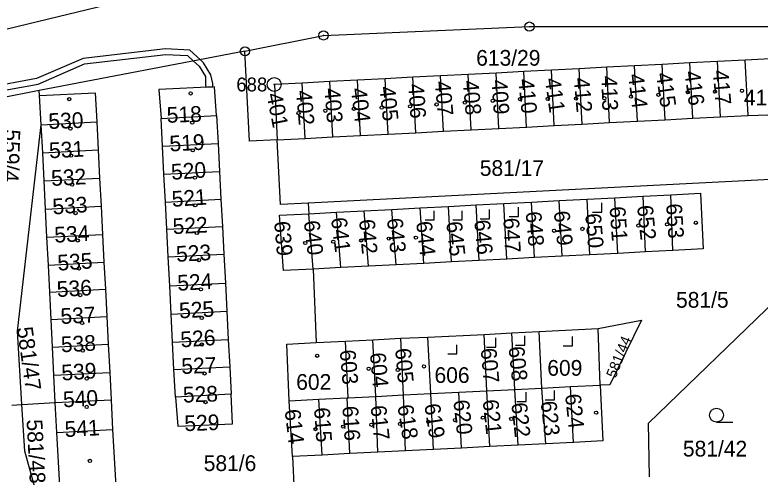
# Model space of a CAD drawing. Extents: x -758582 to -751794, y -998770 to -994350.
# Drawn here: x -756110.2 to -756029.6, y -995556.9 to -995507.3 of the extents above; entities that cross this region are included whole.
import ezdxf

# ---------------------------------------------------------------- set-up
doc = ezdxf.new("R2010")
doc.units = 0
for name, color, linetype in [('Hranice parcel', 7, 'Continuous'), ('Parcelní čísla', 7, 'Continuous'), ('Věcná břemena k části', 7, 'Continuous'), ('Značky bodu BP', 7, 'Continuous'), ('Značky budov', 7, 'Continuous'), ('Značky kultur', 7, 'Continuous')]:
    doc.layers.add(name, color=color, linetype=linetype)

msp = doc.modelspace()

# ---------------------------------------------------------------- linework, layer by layer
at = {"layer": 'Hranice parcel'}
for p, q in [((-756077.08, -995500.54), (-756125.07, -995512.2)), ((-756085.32, -995511.19), (-756107.59, -995515.44)), ((-756043.18, -995512.76), (-756046.18, -995512.92)), ((-756040.19, -995512.61), (-756043.18, -995512.76)), ((-756042.87, -995518.76), (-756043.18, -995512.76)), ((-756037.19, -995512.45), (-756040.19, -995512.61)), ((-756039.88, -995518.6), (-756040.19, -995512.61)), ((-756034.19, -995512.3), (-756037.19, -995512.45)), ((-756036.88, -995518.44), (-756037.19, -995512.45)), ((-756031.2, -995512.14), (-756034.19, -995512.3)), ((-756033.88, -995518.29), (-756034.19, -995512.3)), ((-756030.89, -995518.13), (-756031.2, -995512.14)), ((-756061.16, -995513.69), (-756064.15, -995513.85)), ((-756058.16, -995513.54), (-756061.16, -995513.69)), ((-756060.85, -995519.69), (-756061.16, -995513.69)), ((-756055.17, -995513.38), (-756058.16, -995513.54)), ((-756057.85, -995519.53), (-756058.16, -995513.54)), ((-756052.17, -995513.23), (-756055.17, -995513.38)), ((-756054.86, -995519.38), (-756055.17, -995513.38)), ((-756049.17, -995513.07), (-756052.17, -995513.23)), ((-756051.86, -995519.22), (-756052.17, -995513.23)), ((-756046.18, -995512.92), (-756049.17, -995513.07)), ((-756048.86, -995519.07), (-756049.17, -995513.07)), ((-756045.87, -995518.91), (-756046.18, -995512.92)), ((-756076.14, -995514.47), (-756079.13, -995514.62)), ((-756073.14, -995514.31), (-756076.14, -995514.47)), ((-756075.83, -995520.46), (-756076.14, -995514.47)), ((-756070.15, -995514.16), (-756073.14, -995514.31)), ((-756072.83, -995520.31), (-756073.14, -995514.31)), ((-756067.15, -995514), (-756070.15, -995514.16)), ((-756069.84, -995520.15), (-756070.15, -995514.16)), ((-756064.15, -995513.85), (-756067.15, -995514)), ((-756066.84, -995520), (-756067.15, -995514)), ((-756063.84, -995519.84), (-756064.15, -995513.85)), ((-756078.82, -995520.62), (-756079.13, -995514.62)), ((-756107.59, -995515.44), (-756111.98, -995516.28)), ((-756107.56, -995515.97), (-756107.59, -995515.44)), ((-756107.35, -995519.13), (-756107.56, -995515.97)), ((-756094.4, -995518.46), (-756088.39, -995518.15)), ((-756094.24, -995521.47), (-756094.4, -995518.46)), ((-756088.39, -995518.15), (-756088.23, -995521.16)), ((-756039.88, -995518.6), (-756036.88, -995518.44)), ((-756036.88, -995518.44), (-756033.88, -995518.29)), ((-756033.88, -995518.29), (-756030.89, -995518.13)), ((-756030.89, -995518.13), (-756026.86, -995517.98)), ((-756107.35, -995519.13), (-756101.36, -995518.82)), ((-756107.19, -995522.17), (-756107.35, -995519.13)), ((-756101.36, -995518.82), (-756101.2, -995521.86)), ((-756054.86, -995519.38), (-756051.86, -995519.22)), ((-756051.86, -995519.22), (-756048.86, -995519.07)), ((-756048.86, -995519.07), (-756045.87, -995518.91)), ((-756045.87, -995518.91), (-756042.87, -995518.76)), ((-756042.87, -995518.76), (-756039.88, -995518.6)), ((-756069.84, -995520.15), (-756066.84, -995520)), ((-756066.84, -995520), (-756063.84, -995519.84)), ((-756063.84, -995519.84), (-756060.85, -995519.69)), ((-756060.85, -995519.69), (-756057.85, -995519.53)), ((-756057.85, -995519.53), (-756054.86, -995519.38)), ((-756081.82, -995520.77), (-756078.82, -995520.62)), ((-756078.82, -995520.62), (-756075.83, -995520.46)), ((-756075.83, -995520.46), (-756072.83, -995520.31)), ((-756072.83, -995520.31), (-756069.84, -995520.15)), ((-756094.24, -995521.47), (-756088.23, -995521.16)), ((-756094.08, -995524.5), (-756094.24, -995521.47)), ((-756088.23, -995521.16), (-756088.07, -995524.19)), ((-756107.19, -995522.17), (-756101.2, -995521.86)), ((-756107.04, -995525.22), (-756107.19, -995522.17)), ((-756101.2, -995521.86), (-756101.04, -995524.91)), ((-756107.04, -995525.22), (-756101.04, -995524.91)), ((-756101.04, -995524.91), (-756100.88, -995527.95)), ((-756094.08, -995524.5), (-756088.07, -995524.19)), ((-756093.93, -995527.5), (-756094.08, -995524.5)), ((-756088.07, -995524.19), (-756087.92, -995527.18)), ((-756106.89, -995528.26), (-756107.04, -995525.22)), ((-756028.42, -995525.06), (-756078.5, -995527.61)), ((-756093.93, -995527.5), (-756087.92, -995527.18)), ((-756087.92, -995527.18), (-756087.76, -995530.13)), ((-756054.32, -995527.5), (-756051.32, -995527.34)), ((-756051.32, -995527.34), (-756048.32, -995527.18)), ((-756050.99, -995533.36), (-756051.32, -995527.34)), ((-756048.32, -995527.18), (-756045.32, -995527.03)), ((-756048, -995533.2), (-756048.32, -995527.18)), ((-756045.32, -995527.03), (-756042.26, -995526.87)), ((-756045, -995533.05), (-756045.32, -995527.03)), ((-756042.26, -995526.87), (-756039.26, -995526.71)), ((-756042.01, -995532.89), (-756042.26, -995526.87)), ((-756039.02, -995532.74), (-756039.26, -995526.71)), ((-756106.89, -995528.26), (-756100.88, -995527.95)), ((-756100.88, -995527.95), (-756100.73, -995531)), ((-756093.78, -995530.44), (-756093.93, -995527.5)), ((-756078.5, -995527.61), (-756078.42, -995528.77)), ((-756069.42, -995528.29), (-756066.37, -995528.13)), ((-756066.37, -995528.13), (-756063.32, -995527.97)), ((-756065.97, -995534.13), (-756066.37, -995528.13)), ((-756063.32, -995527.97), (-756060.32, -995527.81)), ((-756062.97, -995533.98), (-756063.32, -995527.97)), ((-756060.32, -995527.81), (-756057.32, -995527.66)), ((-756059.98, -995533.82), (-756060.32, -995527.81)), ((-756057.32, -995527.66), (-756054.32, -995527.5)), ((-756056.98, -995533.67), (-756057.32, -995527.66)), ((-756053.99, -995533.51), (-756054.32, -995527.5)), ((-756106.74, -995531.31), (-756106.89, -995528.26)), ((-756081.57, -995528.93), (-756078.42, -995528.77)), ((-756081.14, -995534.91), (-756081.57, -995528.93)), ((-756078.42, -995528.77), (-756075.42, -995528.61)), ((-756077.94, -995534.75), (-756078.42, -995528.77)), ((-756075.42, -995528.61), (-756072.42, -995528.45)), ((-756074.95, -995534.59), (-756075.42, -995528.61)), ((-756072.42, -995528.45), (-756069.42, -995528.29)), ((-756071.95, -995534.44), (-756072.42, -995528.45)), ((-756068.96, -995534.28), (-756069.42, -995528.29)), ((-756093.78, -995530.44), (-756087.76, -995530.13)), ((-756093.63, -995533.44), (-756093.78, -995530.44)), ((-756087.76, -995530.13), (-756087.61, -995533.12)), ((-756106.74, -995531.31), (-756100.73, -995531)), ((-756106.58, -995534.31), (-756106.74, -995531.31)), ((-756100.73, -995531), (-756100.57, -995534)), ((-756042.01, -995532.89), (-756045, -995533.05)), ((-756039.02, -995532.74), (-756042.01, -995532.89)), ((-756093.63, -995533.44), (-756087.61, -995533.12)), ((-756093.46, -995536.58), (-756093.63, -995533.44)), ((-756087.61, -995533.12), (-756087.44, -995536.27)), ((-756059.98, -995533.82), (-756062.97, -995533.98)), ((-756056.98, -995533.67), (-756059.98, -995533.82)), ((-756053.99, -995533.51), (-756056.98, -995533.67)), ((-756050.99, -995533.36), (-756053.99, -995533.51)), ((-756048, -995533.2), (-756050.99, -995533.36)), ((-756045, -995533.05), (-756048, -995533.2)), ((-756106.58, -995534.31), (-756100.57, -995534)), ((-756106.44, -995537.25), (-756106.58, -995534.31)), ((-756100.57, -995534), (-756100.42, -995536.94)), ((-756074.95, -995534.59), (-756077.94, -995534.75)), ((-756071.95, -995534.44), (-756074.95, -995534.59)), ((-756068.96, -995534.28), (-756071.95, -995534.44)), ((-756065.97, -995534.13), (-756068.96, -995534.28)), ((-756062.97, -995533.98), (-756065.97, -995534.13)), ((-756077.94, -995534.75), (-756081.14, -995534.91)), ((-756077.94, -995534.75), (-756077.6, -995542.71)), ((-756106.44, -995537.25), (-756100.42, -995536.94)), ((-756100.42, -995536.94), (-756100.27, -995539.89)), ((-756093.46, -995536.58), (-756087.44, -995536.27)), ((-756093.31, -995539.63), (-756093.46, -995536.58)), ((-756087.44, -995536.27), (-756087.28, -995539.31)), ((-756106.29, -995540.2), (-756106.44, -995537.25)), ((-756093.31, -995539.63), (-756087.28, -995539.31)), ((-756087.28, -995539.31), (-756087.13, -995542.36)), ((-756106.29, -995540.2), (-756100.27, -995539.89)), ((-756106.14, -995543.2), (-756106.29, -995540.2)), ((-756100.27, -995539.89), (-756100.11, -995542.88)), ((-756093.16, -995542.67), (-756093.31, -995539.63)), ((-756065.54, -995542.12), (-756059.45, -995541.82)), ((-756059.45, -995541.82), (-756056.45, -995541.66)), ((-756059.17, -995547.92), (-756059.45, -995541.82)), ((-756056.45, -995541.66), (-756053.51, -995541.5)), ((-756056.14, -995547.77), (-756056.45, -995541.66)), ((-756053.51, -995541.5), (-756047.11, -995541.17)), ((-756053.2, -995547.62), (-756053.51, -995541.5)), ((-756046.89, -995547.3), (-756047.11, -995541.17)), ((-756093.16, -995542.67), (-756087.13, -995542.36)), ((-756093, -995545.62), (-756093.16, -995542.67)), ((-756087.13, -995542.36), (-756086.97, -995545.31)), ((-756080.8, -995542.87), (-756077.6, -995542.71)), ((-756077.6, -995542.71), (-756074.45, -995542.55)), ((-756074.45, -995542.55), (-756071.48, -995542.39)), ((-756074.14, -995548.67), (-756074.45, -995542.55)), ((-756071.48, -995542.39), (-756068.47, -995542.24)), ((-756071.17, -995548.52), (-756071.48, -995542.39)), ((-756068.47, -995542.24), (-756065.54, -995542.12)), ((-756068.16, -995548.37), (-756068.47, -995542.24)), ((-756065.23, -995548.22), (-756065.54, -995542.12)), ((-756106.14, -995543.2), (-756100.11, -995542.88)), ((-756105.99, -995546.24), (-756106.14, -995543.2)), ((-756100.11, -995542.88), (-756099.95, -995545.93)), ((-756080.54, -995548.99), (-756080.8, -995542.87)), ((-756105.99, -995546.24), (-756099.95, -995545.93)), ((-756099.95, -995545.93), (-756099.8, -995548.88)), ((-756093, -995545.62), (-756086.97, -995545.31)), ((-756092.85, -995548.62), (-756093, -995545.62)), ((-756086.97, -995545.31), (-756086.82, -995548.3)), ((-756105.84, -995549.19), (-756105.99, -995546.24)), ((-756053.2, -995547.62), (-756050.12, -995547.46)), ((-756050.12, -995547.46), (-756046.89, -995547.3)), ((-756049.78, -995553.5), (-756050.12, -995547.46)), ((-756086.82, -995548.3), (-756092.85, -995548.62)), ((-756068.16, -995548.37), (-756065.23, -995548.22)), ((-756065.23, -995548.22), (-756062.18, -995548.07)), ((-756064.92, -995554.26), (-756065.23, -995548.22)), ((-756062.18, -995548.07), (-756059.17, -995547.92)), ((-756061.88, -995554.11), (-756062.18, -995548.07)), ((-756059.17, -995547.92), (-756056.14, -995547.77)), ((-756058.83, -995553.96), (-756059.17, -995547.92)), ((-756056.14, -995547.77), (-756053.2, -995547.62)), ((-756055.78, -995553.8), (-756056.14, -995547.77)), ((-756052.79, -995553.65), (-756053.2, -995547.62)), ((-756105.84, -995549.19), (-756099.8, -995548.88)), ((-756099.8, -995548.88), (-756099.63, -995552.12)), ((-756080.54, -995548.99), (-756077.33, -995548.83)), ((-756080.18, -995555.03), (-756080.54, -995548.99)), ((-756077.33, -995548.83), (-756074.26, -995548.68)), ((-756076.98, -995554.87), (-756077.33, -995548.83)), ((-756074.26, -995548.68), (-756074.14, -995548.67)), ((-756073.97, -995554.72), (-756074.26, -995548.68)), ((-756074.14, -995548.67), (-756071.17, -995548.52)), ((-756071.17, -995548.52), (-756068.16, -995548.37)), ((-756070.96, -995554.57), (-756071.17, -995548.52)), ((-756067.96, -995554.42), (-756068.16, -995548.37)), ((-756110.53, -995549.46), (-756109.44, -995549.4)), ((-756109.44, -995549.4), (-756105.84, -995549.19)), ((-756105.67, -995552.44), (-756105.84, -995549.19)), ((-756105.67, -995552.44), (-756099.63, -995552.12)), ((-756099.63, -995552.12), (-756099.11, -995561.5)), ((-756105.13, -995561.84), (-756105.67, -995552.44)), ((-756058.83, -995553.96), (-756061.88, -995554.11)), ((-756055.78, -995553.8), (-756058.83, -995553.96)), ((-756052.79, -995553.65), (-756055.78, -995553.8)), ((-756049.78, -995553.5), (-756052.79, -995553.65)), ((-756073.97, -995554.72), (-756076.98, -995554.87)), ((-756070.96, -995554.57), (-756073.97, -995554.72)), ((-756067.96, -995554.42), (-756070.96, -995554.57)), ((-756064.92, -995554.26), (-756067.96, -995554.42)), ((-756061.88, -995554.11), (-756064.92, -995554.26)), ((-756076.98, -995554.87), (-756080.18, -995555.03)), ((-756080.18, -995555.03), (-756079.62, -995566.95))]:
    msp.add_line(p, q, dxfattribs=at)
for points in [[(-756085.32, -995511.19), (-756076.82, -995509.47), (-756054.55, -995508.52), (-756023.56, -995508.52)], [(-756081.82, -995520.77), (-756084.82, -995520.93), (-756085.32, -995511.19)], [(-756026.86, -995517.98), (-756027.09, -995511.93), (-756031.2, -995512.14)], [(-756088.39, -995518.15), (-756088.61, -995515.02), (-756094.63, -995515.31), (-756094.4, -995518.46)], [(-756079.13, -995514.62), (-756082.13, -995514.78), (-756081.82, -995520.77)], [(-756107.56, -995515.97), (-756101.52, -995515.67), (-756101.36, -995518.82)], [(-756109.44, -995549.4), (-756109.93, -995541.48), (-756107.35, -995519.13)], [(-756078.5, -995527.61), (-756081.46, -995527.76), (-756081.82, -995520.77)], [(-756039.26, -995526.71), (-756036.06, -995526.54), (-756035.77, -995532.57), (-756039.02, -995532.74)], [(-756041.57, -995557.24), (-756041.68, -995551.43), (-756027.87, -995538.09)], [(-756047.11, -995541.17), (-756042.43, -995540.27), (-756045.85, -995547.27), (-756046.89, -995547.3)], [(-756046.89, -995547.3), (-756046.59, -995553.34), (-756049.78, -995553.5)], [(-756092.85, -995548.62), (-756092.57, -995551.74), (-756086.65, -995551.49), (-756086.82, -995548.3)], [(-756104.61, -995570.77), (-756109.12, -995554.45), (-756109.44, -995549.4)]]:
    msp.add_lwpolyline(points, dxfattribs=at)
at = {"layer": 'Věcná břemena k části'}
msp.add_lwpolyline([(-756113.14, -995515.73), (-756107.68, -995514.73), (-756102.67, -995512.55), (-756093.89, -995511.54), (-756091.52, -995511.66), (-756090.88, -995512.25), (-756090.26, -995512.81), (-756089.58, -995513.92), (-756089.58, -995514.76), (-756089.56, -995515.07), (-756088.79, -995515.03), (-756088.81, -995514.69), (-756089, -995513.72), (-756089.8, -995512.43), (-756090.14, -995512.11), (-756091.28, -995511.08), (-756093.91, -995510.94), (-756102.83, -995511.97), (-756107.86, -995514.15), (-756113.28, -995515.15)], dxfattribs=at)
at = {"layer": 'Značky bodu BP'}
for centre, radius in [((-756054.55, -995508.52), 0.5), ((-756054.55, -995508.52), 0.0303), ((-756076.82, -995509.47), 0.5), ((-756076.82, -995509.47), 0.0303), ((-756085.32, -995511.19), 0.5), ((-756085.32, -995511.19), 0.0303), ((-756082.15, -995514.78), 0.75), ((-756082.15, -995514.78), 0.03)]:
    msp.add_circle(centre, radius, dxfattribs=at)
at = {"layer": 'Značky budov'}
for centre in [(-756031.557, -995515.459), (-756091.197, -995515.749), (-756046.447, -995516.269), (-756043.557, -995516.099), (-756040.597, -995515.899), (-756037.407, -995515.629), (-756034.477, -995515.559), (-756104.327, -995516.369), (-756064.597, -995516.939), (-756061.537, -995516.739), (-756058.517, -995516.539), (-756055.557, -995516.369), (-756052.567, -995516.339), (-756049.507, -995516.299), (-756079.527, -995517.879), (-756076.627, -995517.619), (-756073.537, -995517.409), (-756070.517, -995517.279), (-756067.457, -995517.139), (-756091.027, -995518.909), (-756104.197, -995519.559), (-756090.967, -995521.899), (-756104.117, -995522.479), (-756090.727, -995524.859), (-756104.017, -995525.609), (-756090.697, -995527.859), (-756103.647, -995528.699), (-756039.667, -995529.909), (-756036.547, -995529.739), (-756051.877, -995530.609), (-756048.817, -995530.409), (-756042.767, -995530.039), (-756090.527, -995530.849), (-756069.757, -995531.459), (-756066.827, -995531.349), (-756103.407, -995531.659), (-756078.797, -995531.929), (-756075.767, -995531.789), (-756072.747, -995531.659), (-756090.297, -995533.779), (-756103.277, -995534.679), (-756090.087, -995536.939), (-756103.137, -995537.569), (-756089.987, -995540.029), (-756102.937, -995540.589), (-756102.867, -995543.569), (-756089.987, -995542.919), (-756077.507, -995544.129), (-756065.957, -995545.279), (-756089.687, -995546.049), (-756071.937, -995545.539), (-756068.787, -995545.659), (-756102.437, -995546.599), (-756089.587, -995549.139), (-756102.437, -995549.659), (-756059.577, -995550.829), (-756047.337, -995550.289), (-756071.637, -995551.599), (-756068.547, -995551.499), (-756065.487, -995551.259), (-756062.597, -995551.089), (-756056.517, -995550.959), (-756077.687, -995552.069), (-756074.697, -995551.799), (-756102.097, -995555.509)]:
    msp.add_circle(centre, 0.175, dxfattribs=at)
at = {"layer": 'Značky kultur'}
for p, q in [((-756055.73, -995529.07), (-756055.73, -995528.07)), ((-756046.72, -995528.6), (-756046.72, -995527.6)), ((-756064.84, -995529.44), (-756064.84, -995528.44)), ((-756061.82, -995529.44), (-756061.82, -995528.44)), ((-756058.86, -995529.3), (-756058.86, -995528.3)), ((-756047.721, -995528.6), (-756046.72, -995528.6)), ((-756065.841, -995529.44), (-756064.84, -995529.44)), ((-756062.821, -995529.44), (-756061.82, -995529.44)), ((-756059.861, -995529.3), (-756058.86, -995529.3)), ((-756056.731, -995529.07), (-756055.73, -995529.07)), ((-756058.18, -995543.19), (-756058.18, -995542.19)), ((-756055.06, -995542.99), (-756055.06, -995541.99)), ((-756049.88, -995543.06), (-756049.88, -995542.06)), ((-756062.39, -995543.93), (-756062.39, -995542.93)), ((-756059.181, -995543.19), (-756058.18, -995543.19)), ((-756056.061, -995542.99), (-756055.06, -995542.99)), ((-756050.881, -995543.06), (-756049.88, -995543.06)), ((-756063.391, -995543.93), (-756062.39, -995543.93)), ((-756054.9, -995549.08), (-756054.9, -995548.08)), ((-756051.84, -995548.88), (-756051.84, -995547.88)), ((-756055.901, -995549.08), (-756054.9, -995549.08)), ((-756052.841, -995548.88), (-756051.84, -995548.88)), ((-756034.313, -995551.31), (-756032.563, -995551.31))]:
    msp.add_line(p, q, dxfattribs=at)
msp.add_circle((-756034.313, -995550.56), 0.75, dxfattribs=at)

# ---------------------------------------------------------------- texts
at = {"layer": 'Parcelní čísla'}
for s, p in [('613/29', (-756060.307, -995512.75)), ('418', (-756031.355, -995517.05)), ('581/17', (-756059.917, -995524.67)), ('581/5', (-756038.688, -995538.93)), ('609', (-756052.615, -995546.29)), ('606', (-756064.815, -995547.07)), ('602', (-756079.775, -995547.81)), ('581/42', (-756037.947, -995555.03)), ('581/6', (-756089.778, -995556.6))]:
    msp.add_text(s, height=1.7, dxfattribs=at).set_placement(p)
for s, height, rotation, p in [('415', 1.7, 278, (-756040.865, -995513.605)), ('416', 1.7, 278, (-756037.795, -995513.415)), ('417', 1.7, 275, (-756034.729, -995513.277)), ('407', 1.7, 275, (-756064.789, -995514.457)), ('408', 1.7, 275, (-756061.759, -995514.387)), ('409', 1.7, 274, (-756058.66, -995514.299)), ('410', 1.7, 276, (-756055.778, -995514.236)), ('411', 1.7, 278, (-756052.885, -995514.175)), ('412', 1.7, 275, (-756049.759, -995514.087)), ('413', 1.7, 272, (-756046.78, -995513.865)), ('414', 1.7, 277, (-756043.887, -995513.715)), ('403', 1.7, 275, (-756076.749, -995515.227)), ('404', 1.7, 277, (-756073.867, -995515.235)), ('405', 1.7, 276, (-756070.778, -995515.046)), ('406', 1.7, 274, (-756067.67, -995514.739)), ('401', 1.7, 281, (-756082.998, -995515.849)), ('402', 1.7, 275, (-756079.809, -995515.477)), ('518', 1.7, 2, (-756093.754, -995518.93)), ('530', 1.7, 2, (-756106.554, -995519.6)), ('559/4', 1.7, 268, (-756111.314, -995519.613)), ('519', 1.7, 3, (-756093.437, -995522.03)), ('531', 1.7, 3, (-756106.467, -995522.77)), ('520', 1.7, 4, (-756093.25, -995525.1)), ('532', 1.7, 3, (-756106.237, -995525.76)), ('521', 1.7, 4, (-756093.18, -995528.03)), ('533', 1.7, 4, (-756106.08, -995528.85)), ('651', 1.7, 274, (-756045.88, -995528.019)), ('652', 1.7, 276, (-756042.908, -995527.916)), ('653', 1.7, 274, (-756039.77, -995527.709)), ('648', 1.7, 275, (-756054.969, -995528.577)), ('649', 1.7, 276, (-756051.918, -995528.526)), ('650', 1.7, 275, (-756048.519, -995528.777)), ('522', 1.7, 3, (-756093.097, -995530.98)), ('639', 1.7, 275, (-756082.169, -995529.627)), ('640', 1.7, 277, (-756078.967, -995529.585)), ('641', 1.7, 277, (-756076.017, -995529.255)), ('642', 1.7, 275, (-756072.979, -995529.417)), ('643', 1.7, 276, (-756069.968, -995529.306)), ('644', 1.7, 277, (-756066.817, -995529.665)), ('645', 1.7, 276, (-756063.548, -995529.666)), ('646', 1.7, 275, (-756060.519, -995529.477)), ('647', 1.7, 273, (-756057.37, -995529.242)), ('534', 1.7, 3, (-756105.897, -995531.9)), ('523', 1.7, 3, (-756092.727, -995533.97)), ('535', 1.7, 4, (-756105.54, -995534.93)), ('524', 1.7, 3, (-756092.597, -995537.1)), ('536', 1.7, 3, (-756105.627, -995537.78)), ('525', 1.7, 3, (-756092.397, -995540.09)), ('537', 1.7, 3, (-756105.227, -995540.7)), ('581/47', 1.7, 278, (-756109.991, -995541.109)), ('538', 1.7, 3, (-756105.187, -995543.76)), ('526', 1.7, 4, (-756092.24, -995543.23)), ('581/44', 1.14, 68, (-756045.233, -995546.628)), ('605', 1.7, 275, (-756069.079, -995543.367)), ('607', 1.7, 275, (-756059.819, -995543.357)), ('608', 1.7, 276, (-756056.818, -995543.186)), ('527', 1.7, 2, (-756092.174, -995546.1)), ('603', 1.7, 275, (-756075.069, -995543.537)), ('604', 1.7, 275, (-756071.809, -995543.847)), ('539', 1.7, 4, (-756105.11, -995546.82)), ('528', 1.7, 2, (-756092.004, -995549.2)), ('540', 1.7, 3, (-756104.957, -995549.71)), ('624', 1.7, 276, (-756050.698, -995548.326)), ('620', 1.7, 276, (-756062.778, -995548.966)), ('621', 1.7, 276, (-756059.608, -995548.936)), ('623', 1.7, 276, (-756053.328, -995549.096)), ('614', 1.7, 277, (-756081.037, -995550.005)), ('615', 1.7, 274, (-756077.85, -995549.769)), ('616', 1.7, 274, (-756074.79, -995549.609)), ('617', 1.7, 276, (-756071.738, -995549.566)), ('618', 1.7, 279, (-756068.833, -995549.536)), ('619', 1.7, 279, (-756065.933, -995549.426)), ('622', 1.7, 276, (-756056.508, -995549.266)), ('529', 1.7, 2, (-756091.844, -995552.29)), ('581/48', 1.7, 273, (-756108.945, -995551.052)), ('541', 1.7, 3, (-756104.787, -995552.93))]:
    msp.add_text(s, height=height, rotation=rotation, dxfattribs=at).set_placement(p)
at = {"layer": 'Značky bodu BP'}
msp.add_text('688', height=1.5, dxfattribs=at).set_placement((-756086.253, -995515.53))

doc.saveas('drawing.dxf')
